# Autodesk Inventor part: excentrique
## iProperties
Shininess: 20.0
Length Units: 11269
Angle Units: 11279
Time Units: 11290
Mass Units: 11283
Length Display Precision: 3
Angle Display Precision: 2
Compacted: True
Created: 2003-02
Part Number: excentrique
Material: Par défaut
Document SubType Name: Modélisation
Designer: robert
Density: 1 g/cm^3
Density: 0.0
Volumn: 0.0
Area: 0.0
PropertySet Name: Model Information
Control State: 0
Master: False
Checked Out: False
Author: robert
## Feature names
1. Révolution1 [Revolution]
2. Extrusion1
3. Extrusion2
4. Extrusion3
5. Hélicoïde1
6. Hélicoïde2
7. Hélicoïde3
8. Hélicoïde4
9. Réseau circulaire1 [Circular Pattern]
